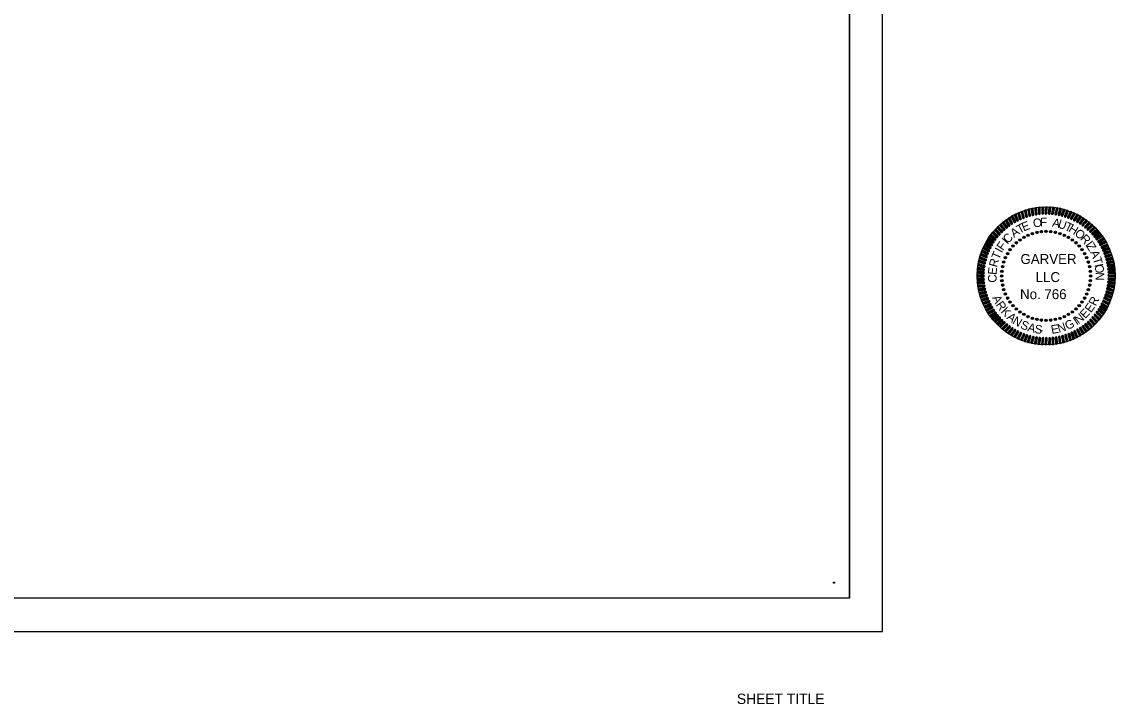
# Model space of a CAD drawing. Extents: x 0 to 19, y -0.6 to 11.2.
# Drawn here: x 9.51 to 19.02, y -0.63 to 5.3 of the extents above; entities that cross this region are included whole.
import ezdxf

# ---------------------------------------------------------------- set-up
doc = ezdxf.new("R2010")
doc.units = 0
for name, color, linetype in [('G-ANNO-TEXT', 7, 'Continuous'), ('G-Border-Paper', 7, 'Continuous'), ('G-Border-Sheet', 7, 'Continuous'), ('G-No Plot-Anchor', 7, 'Continuous'), ('G-No Plot-Border-1', 7, 'Continuous'), ('G-No Plot-Border-2', 7, 'Continuous'), ('G-No Plot-Stamp-1', 7, 'Continuous')]:
    doc.layers.add(name, color=color, linetype=linetype)

# ---------------------------------------------------------------- blocks, each defined once
blk = doc.blocks.new('SEALDO')
at = {"layer": 'G-ANNO-TEXT'}
for radius in [0.0396, 0.0305, 0.0213, 0.0122, 0.00305]:
    blk.add_circle((1.403, -0.456), radius, dxfattribs=at)
blk = doc.blocks.new('SEALRI')
at = {"layer": 'G-ANNO-TEXT'}
for p, q in [((-0.023, 2.258), (-0.038, 2.081)), ((-0.008, 2.281), (-0.028, 2.056)), ((0.004, 2.286), (-0.016, 2.049)), ((0.016, 2.285), (-0.004, 2.048)), ((0.028, 2.278), (0.008, 2.052)), ((0.023, 2.076), (0.038, 2.253))]:
    blk.add_line(p, q, dxfattribs=at)
for centre, start, end in [((0.008, 2.256), 355, 175), ((-0.008, 2.078), 175, 355)]:
    blk.add_arc(centre, 0.0305, start, end, dxfattribs=at)

msp = doc.modelspace()

# ---------------------------------------------------------------- linework, layer by layer
at = {"layer": 'G-Border-Paper'}
msp.add_lwpolyline([(17, 11), (0, 11), (0, 0), (17, 0)], close=True, dxfattribs=at)
at = {"layer": 'G-Border-Sheet'}
for q in [(16.7116, 10.7116), (0.758, 0.2884)]:
    msp.add_line((16.7116, 0.2884), q, dxfattribs=at)
at = {"layer": 'G-No Plot-Anchor'}
msp.add_circle((16.5766, 0.4234), 0.005, dxfattribs=at)
at = {"layer": 'G-No Plot-Border-1'}
msp.add_lwpolyline([(0.758, 0.2884), (0.758, 10.7116), (12.7381, 10.7116), (12.7381, 10.2161), (14.7206, 10.2161), (14.7206, 10.0611), (15.4366, 10.0611), (15.4366, 8.5861), (16.7116, 8.5861), (16.7116, 0.2884)], close=True, dxfattribs=at)
at = {"layer": 'G-No Plot-Border-2'}
msp.add_lwpolyline([(0.758, 10.7116), (11.4739, 10.7116), (11.4739, 9.2366), (12.7381, 9.2366), (12.7381, 10.2161), (14.7206, 10.2161), (14.7206, 10.0611), (16.7116, 10.0611), (16.7116, 0.2884), (0.758, 0.2884)], close=True, dxfattribs=at)
at = {"layer": 'G-No Plot-Stamp-1'}
msp.add_circle((18.4222, 3.0925), 0.6, dxfattribs=at)
msp.add_circle((18.4222, 3.0925), 0.6, dxfattribs=at)

# ---------------------------------------------------------------- block references
at = {"layer": 'G-ANNO-TEXT'}
for name, xscale, yscale, rotation in [('SEALRI', 0.2624620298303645, 0.2624620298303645, 30.00000000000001), ('SEALRI', 0.2624620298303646, 0.26246202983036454, 26.99999999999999), ('SEALRI', 0.26246202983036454, 0.26246202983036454, 23.99999999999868), ('SEALRI', 0.26246202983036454, 0.26246202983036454, 20.999999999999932), ('SEALRI', 0.2624620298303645, 0.26246202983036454, 18), ('SEALRI', 0.2624620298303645, 0.2624620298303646, 15.000000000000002), ('SEALRI', 0.2624620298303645, 0.2624620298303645, 12.000000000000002), ('SEALRI', 0.2624620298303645, 0.2624620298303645, 9), ('SEALRI', 0.2624620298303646, 0.26246202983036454, 5.999999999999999), ('SEALRI', 0.2624620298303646, 0.2624620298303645, 3.0000000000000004), ('SEALRI', 0.26246202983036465, 0.2624620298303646, -2.9999999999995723), ('SEALRI', 0.2624620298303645, 0.2624620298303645, -5.9999999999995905), ('SEALRI', 0.2624620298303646, 0.26246202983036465, -8.999999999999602), ('SEALRI', 0.2624620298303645, 0.26246202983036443, -11.999999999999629), ('SEALRI', 0.2624620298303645, 0.2624620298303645, -14.999999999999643), ('SEALRI', 0.26246202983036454, 0.2624620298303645, -17.99999999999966), ('SEALRI', 0.2624620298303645, 0.2624620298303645, -20.999999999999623), ('SEALRI', 0.2624620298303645, 0.2624620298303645, -23.99999999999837), ('SEALRI', 0.26246202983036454, 0.2624620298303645, -26.99999999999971), ('SEALRI', 0.26246202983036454, 0.2624620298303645, -29.99999999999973), ('SEALRI', 0.26246202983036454, 0.2624620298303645, 44.999999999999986), ('SEALRI', 0.26246202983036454, 0.2624620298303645, 41.999999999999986), ('SEALRI', 0.26246202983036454, 0.26246202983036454, 38.999999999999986), ('SEALRI', 0.2624620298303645, 0.2624620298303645, 36), ('SEALRI', 0.2624620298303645, 0.26246202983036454, 33), ('SEALRI', 0.26246202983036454, 0.2624620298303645, -32.999999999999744), ('SEALRI', 0.2624620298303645, 0.2624620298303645, -35.999999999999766), ('SEALRI', 0.2624620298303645, 0.2624620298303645, -38.99999999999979), ('SEALRI', 0.26246202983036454, 0.2624620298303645, -41.99999999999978), ('SEALRI', 0.26246202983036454, 0.2624620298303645, -44.99999999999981), ('SEALRI', 0.26246202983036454, 0.2624620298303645, 56.99999999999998), ('SEALRI', 0.2624620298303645, 0.2624620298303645, 54), ('SEALRI', 0.26246202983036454, 0.26246202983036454, 50.99999999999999), ('SEALRI', 0.26246202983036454, 0.2624620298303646, 48), ('SEALDO', 0.26246202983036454, 0.2624620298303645, 138), ('SEALDO', 0.2624620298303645, 0.26246202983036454, 131.99999999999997), ('SEALDO', 0.2624620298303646, 0.26246202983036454, 125.99999999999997), ('SEALDO', 0.26246202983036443, 0.26246202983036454, 119.99999999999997), ('SEALDO', 0.2624620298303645, 0.26246202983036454, 113.99999999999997), ('SEALDO', 0.26246202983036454, 0.26246202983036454, 107.99999999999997), ('SEALDO', 0.26246202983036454, 0.26246202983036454, 101.99999999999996), ('SEALDO', 0.2624620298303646, 0.2624620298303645, 95.99999999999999), ('SEALDO', 0.26246202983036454, 0.26246202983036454, 90), ('SEALDO', 0.2624620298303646, 0.26246202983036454, 83.99999999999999), ('SEALDO', 0.2624620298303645, 0.26246202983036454, 77.99999999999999), ('SEALRI', 0.26246202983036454, 0.2624620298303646, -47.99999999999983), ('SEALRI', 0.2624620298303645, 0.26246202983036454, -50.999999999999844), ('SEALRI', 0.2624620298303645, 0.26246202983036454, -53.99999999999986), ('SEALRI', 0.26246202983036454, 0.26246202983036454, -56.999999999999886), ('SEALRI', 0.26246202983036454, 0.26246202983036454, 65.99999999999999), ('SEALRI', 0.26246202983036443, 0.2624620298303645, 63), ('SEALRI', 0.2624620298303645, 0.2624620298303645, 59.999999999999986), ('SEALDO', 0.2624620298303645, 0.26246202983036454, 162.00000000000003), ('SEALDO', 0.26246202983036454, 0.26246202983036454, 156.00000000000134), ('SEALDO', 0.26246202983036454, 0.2624620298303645, 150), ('SEALDO', 0.2624620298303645, 0.2624620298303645, 144), ('SEALDO', 0.2624620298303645, 0.26246202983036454, 72), ('SEALDO', 0.26246202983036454, 0.2624620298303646, 66.00000000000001), ('SEALDO', 0.26246202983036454, 0.2624620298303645, 60.00000000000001), ('SEALDO', 0.2624620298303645, 0.2624620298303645, 54), ('SEALRI', 0.2624620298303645, 0.26246202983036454, -59.99999999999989), ('SEALRI', 0.26246202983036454, 0.2624620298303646, -62.99999999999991), ('SEALRI', 0.26246202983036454, 0.2624620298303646, -65.99999999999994), ('SEALRI', 0.2624620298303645, 0.26246202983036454, 75.00000000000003), ('SEALRI', 0.2624620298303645, 0.26246202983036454, 72), ('SEALRI', 0.26246202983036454, 0.2624620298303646, 68.99999999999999), ('SEALDO', 0.2624620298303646, 0.2624620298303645, 174.00000000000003), ('SEALDO', 0.26246202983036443, 0.2624620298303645, 168.00000000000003), ('SEALDO', 0.26246202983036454, 0.26246202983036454, 48.00000000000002), ('SEALDO', 0.26246202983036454, 0.2624620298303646, 42.00000000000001), ('SEALRI', 0.26246202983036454, 0.26246202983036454, -68.99999999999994), ('SEALRI', 0.2624620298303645, 0.26246202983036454, -71.99999999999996), ('SEALRI', 0.26246202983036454, 0.2624620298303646, -74.99999999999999), ('SEALRI', 0.2624620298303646, 0.26246202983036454, 84.00000000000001), ('SEALRI', 0.2624620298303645, 0.2624620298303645, 81), ('SEALRI', 0.2624620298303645, 0.2624620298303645, 78.00000000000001), ('SEALDO', 0.2624620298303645, 0.26246202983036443, -167.99999999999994), ('SEALDO', 0.26246202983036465, 0.26246202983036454, -173.99999999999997), ('SEALDO', 0.26246202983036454, 0.26246202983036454, -179.99999999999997), ('SEALDO', 0.2624620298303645, 0.2624620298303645, 36), ('SEALDO', 0.26246202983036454, 0.2624620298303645, 29.999999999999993), ('SEALDO', 0.26246202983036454, 0.2624620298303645, 23.99999999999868), ('SEALRI', 0.2624620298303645, 0.2624620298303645, -78), ('SEALRI', 0.2624620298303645, 0.2624620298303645, -81.00000000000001), ('SEALRI', 0.2624620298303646, 0.2624620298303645, -84.00000000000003), ('SEALRI', 0.26246202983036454, 0.26246202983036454, 90.00000000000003), ('SEALRI', 0.26246202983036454, 0.26246202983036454, 87.00000000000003), ('SEALRI', 0.2624620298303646, 0.2624620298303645, 93), ('SEALRI', 0.2624620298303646, 0.26246202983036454, 96.00000000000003), ('SEALDO', 0.2624620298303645, 0.26246202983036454, -161.99999999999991), ('SEALDO', 0.2624620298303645, 0.26246202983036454, -156.00000000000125), ('SEALDO', 0.2624620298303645, 0.2624620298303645, 12.000000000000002), ('SEALDO', 0.2624620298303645, 0.26246202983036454, 18), ('SEALRI', 0.26246202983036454, 0.2624620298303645, -96.0000000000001), ('SEALRI', 0.26246202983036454, 0.26246202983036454, -87.00000000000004), ('SEALRI', 0.2624620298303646, 0.26246202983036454, -93.00000000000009), ('SEALRI', 0.26246202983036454, 0.26246202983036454, -90.00000000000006), ('SEALRI', 0.26246202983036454, 0.26246202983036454, 99.00000000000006), ('SEALRI', 0.2624620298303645, 0.2624620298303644, 102.00000000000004), ('SEALRI', 0.26246202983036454, 0.2624620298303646, 105.00000000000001), ('SEALDO', 0.26246202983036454, 0.26246202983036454, -149.99999999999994), ('SEALDO', 0.2624620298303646, 0.26246202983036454, -143.99999999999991), ('SEALDO', 0.26246202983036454, 0.2624620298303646, -137.9999999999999), ('SEALDO', 0.2624620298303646, 0.26246202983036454, 5.999999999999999), ('SEALRI', 0.26246202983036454, 0.2624620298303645, -105.00000000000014), ('SEALRI', 0.2624620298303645, 0.26246202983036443, -102.00000000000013), ('SEALRI', 0.26246202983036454, 0.2624620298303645, -99.00000000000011), ('SEALRI', 0.2624620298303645, 0.26246202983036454, 108.00000000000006), ('SEALRI', 0.2624620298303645, 0.2624620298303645, 111.00000000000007), ('SEALRI', 0.26246202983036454, 0.26246202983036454, 114.00000000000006), ('SEALRI', 0.26246202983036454, 0.26246202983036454, 117.00000000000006), ('SEALDO', 0.26246202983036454, 0.26246202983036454, -131.99999999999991), ('SEALDO', 0.2624620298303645, 0.26246202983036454, -125.9999999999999), ('SEALDO', 0.2624620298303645, 0.2624620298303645, -18.000000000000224), ('SEALDO', 0.2624620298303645, 0.26246202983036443, -12.000000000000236), ('SEALDO', 0.26246202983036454, 0.2624620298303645, -6.000000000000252), ('SEALRI', 0.26246202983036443, 0.2624620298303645, -117.00000000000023), ('SEALRI', 0.26246202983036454, 0.2624620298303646, -114.0000000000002), ('SEALRI', 0.2624620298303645, 0.26246202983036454, -111.00000000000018), ('SEALRI', 0.26246202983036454, 0.2624620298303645, -108.00000000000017), ('SEALRI', 0.2624620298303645, 0.2624620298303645, 120.00000000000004), ('SEALRI', 0.2624620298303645, 0.2624620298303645, 123.00000000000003), ('SEALRI', 0.26246202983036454, 0.2624620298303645, 126.00000000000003), ('SEALRI', 0.26246202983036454, 0.26246202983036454, 129.00000000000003), ('SEALDO', 0.2624620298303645, 0.26246202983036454, -119.99999999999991), ('SEALDO', 0.26246202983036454, 0.26246202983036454, -113.99999999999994), ('SEALDO', 0.26246202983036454, 0.26246202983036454, -107.99999999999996), ('SEALDO', 0.2624620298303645, 0.26246202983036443, -101.99999999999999), ('SEALDO', 0.2624620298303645, 0.2624620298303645, -42.00000000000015), ('SEALDO', 0.26246202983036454, 0.2624620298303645, -36.00000000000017), ('SEALDO', 0.2624620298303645, 0.26246202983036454, -30.00000000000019), ('SEALDO', 0.26246202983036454, 0.2624620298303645, -23.999999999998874), ('SEALRI', 0.2624620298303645, 0.26246202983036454, -129.00000000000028), ('SEALRI', 0.26246202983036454, 0.2624620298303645, -126.00000000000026), ('SEALRI', 0.2624620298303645, 0.26246202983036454, -123.00000000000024), ('SEALRI', 0.26246202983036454, 0.2624620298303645, -120.00000000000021), ('SEALRI', 0.26246202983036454, 0.2624620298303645, 132), ('SEALRI', 0.2624620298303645, 0.26246202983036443, 135), ('SEALRI', 0.26246202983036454, 0.2624620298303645, 138), ('SEALRI', 0.2624620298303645, 0.26246202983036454, 140.99999999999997), ('SEALRI', 0.2624620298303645, 0.2624620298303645, 144), ('SEALDO', 0.2624620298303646, 0.26246202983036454, -96), ('SEALDO', 0.26246202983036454, 0.26246202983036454, -90.00000000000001), ('SEALDO', 0.2624620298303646, 0.2624620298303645, -84.00000000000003), ('SEALDO', 0.26246202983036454, 0.26246202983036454, -78.00000000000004), ('SEALDO', 0.26246202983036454, 0.2624620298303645, -72.00000000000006), ('SEALDO', 0.2624620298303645, 0.26246202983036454, -66.00000000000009), ('SEALDO', 0.26246202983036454, 0.26246202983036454, -60.0000000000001), ('SEALDO', 0.2624620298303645, 0.26246202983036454, -54.00000000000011), ('SEALDO', 0.26246202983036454, 0.2624620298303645, -48.00000000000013), ('SEALRI', 0.2624620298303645, 0.26246202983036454, -144.00000000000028), ('SEALRI', 0.2624620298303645, 0.2624620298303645, -141.0000000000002), ('SEALRI', 0.2624620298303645, 0.2624620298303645, -138.00000000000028), ('SEALRI', 0.2624620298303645, 0.2624620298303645, -135.00000000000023), ('SEALRI', 0.2624620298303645, 0.26246202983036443, -132.00000000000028), ('SEALRI', 0.2624620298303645, 0.26246202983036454, 146.99999999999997), ('SEALRI', 0.2624620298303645, 0.26246202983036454, 149.99999999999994), ('SEALRI', 0.2624620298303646, 0.26246202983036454, 152.99999999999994), ('SEALRI', 0.2624620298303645, 0.2624620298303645, 156.00000000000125), ('SEALRI', 0.2624620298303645, 0.26246202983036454, 159), ('SEALRI', 0.26246202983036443, 0.26246202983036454, 161.99999999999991), ('SEALRI', 0.2624620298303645, 0.26246202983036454, 164.99999999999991), ('SEALRI', 0.2624620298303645, 0.26246202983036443, 167.99999999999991), ('SEALRI', 0.2624620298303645, 0.2624620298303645, -168.0000000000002), ('SEALRI', 0.2624620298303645, 0.2624620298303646, -165.0000000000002), ('SEALRI', 0.2624620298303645, 0.26246202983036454, -162.00000000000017), ('SEALRI', 0.2624620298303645, 0.26246202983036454, -159.00000000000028), ('SEALRI', 0.26246202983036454, 0.2624620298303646, -156.00000000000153), ('SEALRI', 0.2624620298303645, 0.2624620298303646, -153.00000000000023), ('SEALRI', 0.2624620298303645, 0.26246202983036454, -150.00000000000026), ('SEALRI', 0.26246202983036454, 0.2624620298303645, -147.00000000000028), ('SEALRI', 0.26246202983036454, 0.2624620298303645, 170.9999999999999), ('SEALRI', 0.26246202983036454, 0.2624620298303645, 173.9999999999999), ('SEALRI', 0.2624620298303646, 0.2624620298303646, 176.9999999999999), ('SEALRI', 0.26246202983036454, 0.26246202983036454, 179.99999999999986), ('SEALRI', 0.2624620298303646, 0.26246202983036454, -177.00000000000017), ('SEALRI', 0.2624620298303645, 0.2624620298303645, -174.00000000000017), ('SEALRI', 0.26246202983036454, 0.2624620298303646, -171.00000000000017)]:
    msp.add_blockref(name, (18.4223, 3.0925), dxfattribs=dict(at, xscale=xscale, yscale=yscale, rotation=rotation))
at = {"layer": 'G-ANNO-TEXT', "xscale": 0.26246202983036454, "yscale": 0.26246202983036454}
for name in ['SEALRI', 'SEALDO']:
    msp.add_blockref(name, (18.4223, 3.0925), dxfattribs=at)

# ---------------------------------------------------------------- texts
at = {"layer": 'G-ANNO-TEXT'}
for s, rotation, p in [('T', 28.2771, (18.1905, 3.4573)), ('E', 21.61044, (18.2267, 3.4785)), ('O', 8.2771, (18.3136, 3.5123)), ('F', 1.61044, (18.3705, 3.522)), ('A', 348.2771, (18.4707, 3.5227)), ('U', 341.27715, (18.5176, 3.5152)), ('T', 334.94377, (18.5765, 3.4962)), ('H', 328.2771, (18.6103, 3.4828)), ('I', 49.74076, (18.0858, 3.3622)), ('C', 44.38813, (18.0896, 3.3699)), ('A', 34.94377, (18.1428, 3.4228)), ('O', 319.7874, (18.6645, 3.452)), ('R', 311.99331, (18.7137, 3.4128)), ('I', 61.61044, (18.0378, 3.2871)), ('F', 54.94377, (18.0468, 3.3073)), ('I', 307.00814, (18.7595, 3.3613)), ('Z', 301.61044, (18.7683, 3.3523)), ('R', 74.94377, (17.9951, 3.1629)), ('T', 67.43139, (18.0126, 3.2289)), ('A', 292.97516, (18.8037, 3.2978)), ('T', 286.3085, (18.8272, 3.2435)), ('E', 83.89849, (17.9897, 3.0987)), ('I', 281.61044, (18.8422, 3.1908)), ('O', 276.48226, (18.8451, 3.1881)), ('C', 91.88416, (17.993, 3.0347)), ('N', 268.2771, (18.8545, 3.1248)), ('A', 296.57465, (17.9514, 2.9025)), ('R', 304.61826, (17.981, 2.8408)), ('E', 54.73091, (18.8126, 2.7672)), ('R', 63.09594, (18.8543, 2.8247)), ('K', 313.3805, (18.0231, 2.778)), ('A', 321.25836, (18.0738, 2.7232)), ('N', 38.98211, (18.705, 2.6701)), ('E', 46.68075, (18.7629, 2.7159)), ('N', 329.10994, (18.1231, 2.6817)), ('S', 337.62936, (18.1923, 2.6396)), ('A', 345.40726, (18.2555, 2.613)), ('S', 352.80457, (18.3191, 2.5952)), ('E', 10.06947, (18.4713, 2.5871)), ('N', 17.86862, (18.5341, 2.5965)), ('G', 26.41319, (18.608, 2.6194)), ('I', 32.97899, (18.6876, 2.6612)), ('-', 0.83848, (18.3644, 2.5854))]:
    msp.add_text(s, height=0.075, rotation=rotation, dxfattribs=at).set_placement(p)
for s, height, p in [('GARVER', 0.0864, (18.1993, 3.1961)), ('LLC', 0.0864, (18.3314, 3.039)), ('No. 766', 0.0864, (18.1956, 2.8903)), ('SHEET TITLE', 0.09, (15.7319, -0.6318))]:
    msp.add_text(s, height=height, dxfattribs=at).set_placement(p)

doc.saveas('drawing.dxf')
